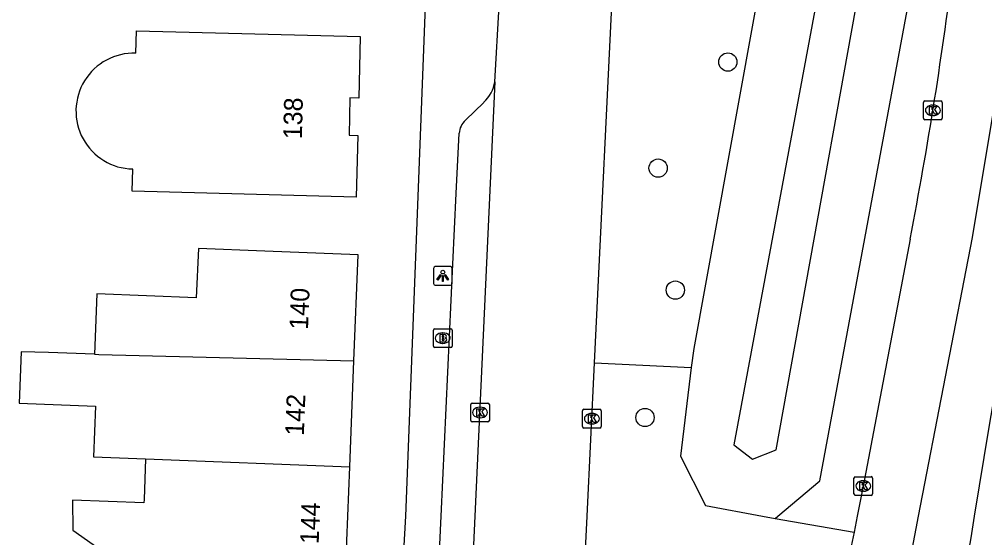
# Model space of a CAD drawing. Extents: x 160158 to 160921, y 381517 to 382041.
# Drawn here: x 160474 to 160525.6, y 381748.8 to 381776.6 of the extents above; entities that cross this region are included whole.
import ezdxf

# ---------------------------------------------------------------- set-up
doc = ezdxf.new("R2010")
doc.units = 0
for name, color, linetype in [('IMGEO_Berm_groen', 7, 'Continuous'), ('IMGEO_Boom', 7, 'Continuous'), ('IMGEO_Brandkraan', 7, 'Continuous'), ('IMGEO_Kolk', 7, 'Continuous'), ('IMGEO_Lichtpunt', 7, 'Continuous'), ('IMGEO_Pand', 7, 'Continuous'), ('IMGEO_Pand_nummerreeks', 7, 'Continuous'), ('IMGEO_Rijbaan_lokaal_open', 7, 'Continuous'), ('IMGEO_Rijbaan_regionaal_gesloten', 7, 'Continuous'), ('IMGEO_Voetpad_open', 7, 'Continuous')]:
    doc.layers.add(name, color=color, linetype=linetype)

msp = doc.modelspace()

# ---------------------------------------------------------------- linework, layer by layer
at = {"layer": 'IMGEO_Berm_groen'}
for points in [[(160520.28, 381829.952), (160520.063, 381825.981), (160517.843, 381805.586), (160514.368, 381782.689), (160510.053, 381758.978), (160509.927, 381757.953)], [(160518.254, 381786.275), (160512.205, 381753.816), (160513.2, 381753.054), (160514.475, 381753.541), (160520.343, 381786.102)], [(160514.409, 381749.874), (160514.559, 381750), (160516.8, 381751.896), (160523.052, 381785.526)], [(160504.746, 381758.207), (160509.927, 381757.953)], [(160509.927, 381757.953), (160509.344, 381753.204), (160510.68, 381750.562), (160513.728, 381750), (160514.409, 381749.874)], [(160514.409, 381749.874), (160518.635, 381749.141)]]:
    msp.add_lwpolyline(points, dxfattribs=at)
at = {"layer": 'IMGEO_Boom'}
for centre in [(160511.882, 381774.3), (160508.151, 381768.624), (160509.07, 381762.096), (160507.447, 381755.276)]:
    msp.add_circle(centre, 0.489, dxfattribs=at)
at = {"layer": 'IMGEO_Brandkraan'}
for p, q in [((160496.125, 381759.1), (160496.125, 381759.952)), ((160496.2, 381760.026), (160497.052, 381760.026)), ((160496.613, 381759.806), (160496.638, 381759.806)), ((160497.126, 381759.952), (160497.126, 381759.1)), ((160497.052, 381759.026), (160496.2, 381759.026)), ((160496.636, 381759.246), (160496.611, 381759.246))]:
    msp.add_line(p, q, dxfattribs=at)
for points in [[(160496.125, 381759.1), (160496.125, 381759.952)], [(160496.2, 381760.026), (160497.052, 381760.026)], [(160496.473, 381759.726), (160496.473, 381759.326), (160496.686, 381759.326)], [(160496.704, 381759.726), (160496.473, 381759.726)], [(160496.652, 381759.645), (160496.598, 381759.645), (160496.598, 381759.569)], [(160496.598, 381759.569), (160496.651, 381759.569)], [(160497.126, 381759.952), (160497.126, 381759.1)], [(160497.052, 381759.026), (160496.2, 381759.026)], [(160496.66, 381759.493), (160496.598, 381759.493), (160496.598, 381759.412)], [(160496.598, 381759.412), (160496.66, 381759.412)]]:
    msp.add_lwpolyline(points, dxfattribs=at)
for centre, radius, start, end in [((160496.202, 381759.95), 0.0765, 91.552, 178.448), ((160496.202, 381759.95), 0.0765, 91.552, 178.448), ((160496.653, 381759.607), 0.0379, 267.8285, 90.9355), ((160496.708, 381759.581), 0.145, 59.4692, 91.5367), ((160496.733, 381759.628), 0.0922, 285.5137, 58.1501), ((160496.738, 381759.436), 0.105, 301.3115, 78.989), ((160497.05, 381759.95), 0.0765, 1.552, 88.448), ((160497.05, 381759.95), 0.0765, 1.552, 88.448), ((160496.202, 381759.102), 0.0765, 181.552, 268.448), ((160496.202, 381759.102), 0.0765, 181.552, 268.448), ((160496.661, 381759.452), 0.0404, 269.8759, 90.5077), ((160496.692, 381759.577), 0.251, 268.6676, 293.5347), ((160497.05, 381759.102), 0.0765, 271.552, 358.448), ((160497.05, 381759.102), 0.0765, 271.552, 358.448)]:
    msp.add_arc(centre, radius, start, end, dxfattribs=at)
for centre, major_axis, ratio, start_param, end_param in [((160496.612, 381759.526), (-0.387, 0.002), 0.722429, 4.712389, 7.853982), ((160496.637, 381759.526), (-0.39, 0.002), 0.717154, 1.570796, 4.712389)]:
    msp.add_ellipse(centre, major_axis=major_axis, ratio=ratio, start_param=start_param, end_param=end_param, dxfattribs=at)
at = {"layer": 'IMGEO_Kolk'}
for p, q in [((160522.353, 381771.29), (160522.353, 381772.142)), ((160522.428, 381772.216), (160523.28, 381772.216)), ((160522.841, 381771.996), (160522.866, 381771.996)), ((160523.354, 381772.142), (160523.354, 381771.29)), ((160522.864, 381771.436), (160522.839, 381771.436)), ((160523.28, 381771.216), (160522.428, 381771.216)), ((160498.12, 381755.121), (160498.12, 381755.973)), ((160498.195, 381756.047), (160499.047, 381756.047)), ((160499.121, 381755.973), (160499.121, 381755.121)), ((160498.608, 381755.827), (160498.633, 381755.827)), ((160504.104, 381754.789), (160504.104, 381755.641)), ((160504.179, 381755.715), (160505.031, 381755.715)), ((160504.592, 381755.495), (160504.617, 381755.495)), ((160505.105, 381755.641), (160505.105, 381754.789)), ((160499.047, 381755.047), (160498.195, 381755.047)), ((160498.631, 381755.267), (160498.606, 381755.267)), ((160504.615, 381754.935), (160504.59, 381754.935)), ((160505.031, 381754.715), (160504.179, 381754.715)), ((160518.628, 381751.185), (160518.628, 381752.037)), ((160518.703, 381752.111), (160519.555, 381752.111)), ((160519.116, 381751.891), (160519.141, 381751.891)), ((160519.629, 381752.037), (160519.629, 381751.185)), ((160519.139, 381751.331), (160519.114, 381751.331)), ((160519.555, 381751.111), (160518.703, 381751.111))]:
    msp.add_line(p, q, dxfattribs=at)
for points in [[(160522.353, 381771.29), (160522.353, 381772.142)], [(160522.428, 381772.216), (160523.28, 381772.216)], [(160523.354, 381772.142), (160523.354, 381771.29)], [(160522.674, 381771.916), (160522.797, 381771.916), (160522.797, 381771.765), (160522.927, 381771.916), (160523.091, 381771.916), (160522.945, 381771.765), (160523.098, 381771.516), (160522.946, 381771.516), (160522.861, 381771.68), (160522.797, 381771.613), (160522.797, 381771.516), (160522.674, 381771.516), (160522.674, 381771.916)], [(160523.28, 381771.216), (160522.428, 381771.216)], [(160498.12, 381755.121), (160498.12, 381755.973)], [(160498.195, 381756.047), (160499.047, 381756.047)], [(160499.121, 381755.973), (160499.121, 381755.121)], [(160498.441, 381755.747), (160498.564, 381755.747), (160498.564, 381755.596), (160498.694, 381755.747), (160498.858, 381755.747), (160498.712, 381755.596), (160498.865, 381755.347), (160498.713, 381755.347), (160498.628, 381755.511), (160498.564, 381755.444), (160498.564, 381755.347), (160498.441, 381755.347), (160498.441, 381755.747)], [(160504.104, 381754.789), (160504.104, 381755.641)], [(160504.179, 381755.715), (160505.031, 381755.715)], [(160504.425, 381755.415), (160504.548, 381755.415), (160504.548, 381755.264), (160504.678, 381755.415), (160504.842, 381755.415), (160504.696, 381755.264), (160504.849, 381755.015), (160504.697, 381755.015), (160504.612, 381755.179), (160504.548, 381755.112), (160504.548, 381755.015), (160504.425, 381755.015), (160504.425, 381755.415)], [(160505.105, 381755.641), (160505.105, 381754.789)], [(160499.047, 381755.047), (160498.195, 381755.047)], [(160505.031, 381754.715), (160504.179, 381754.715)], [(160518.628, 381751.185), (160518.628, 381752.037)], [(160518.703, 381752.111), (160519.555, 381752.111)], [(160518.949, 381751.811), (160519.072, 381751.811), (160519.072, 381751.66), (160519.202, 381751.811), (160519.366, 381751.811), (160519.22, 381751.66), (160519.373, 381751.411), (160519.221, 381751.411), (160519.136, 381751.575), (160519.072, 381751.508), (160519.072, 381751.411), (160518.949, 381751.411), (160518.949, 381751.811)], [(160519.629, 381752.037), (160519.629, 381751.185)], [(160519.555, 381751.111), (160518.703, 381751.111)]]:
    msp.add_lwpolyline(points, dxfattribs=at)
for centre, start, end in [((160522.43, 381772.14), 91.552, 178.448), ((160522.43, 381772.14), 91.552, 178.448), ((160523.278, 381772.14), 1.552, 88.448), ((160523.278, 381772.14), 1.552, 88.448), ((160522.43, 381771.292), 181.552, 268.448), ((160522.43, 381771.292), 181.552, 268.448), ((160523.278, 381771.292), 271.552, 358.448), ((160523.278, 381771.292), 271.552, 358.448), ((160498.197, 381755.971), 91.552, 178.448), ((160498.197, 381755.971), 91.552, 178.448), ((160499.045, 381755.971), 1.552, 88.448), ((160499.045, 381755.971), 1.552, 88.448), ((160504.181, 381755.639), 91.552, 178.448), ((160504.181, 381755.639), 91.552, 178.448), ((160505.029, 381755.639), 1.552, 88.448), ((160505.029, 381755.639), 1.552, 88.448), ((160498.197, 381755.123), 181.552, 268.448), ((160498.197, 381755.123), 181.552, 268.448), ((160499.045, 381755.123), 271.552, 358.448), ((160499.045, 381755.123), 271.552, 358.448), ((160504.181, 381754.791), 181.552, 268.448), ((160504.181, 381754.791), 181.552, 268.448), ((160505.029, 381754.791), 271.552, 358.448), ((160505.029, 381754.791), 271.552, 358.448), ((160518.705, 381752.035), 91.552, 178.448), ((160518.705, 381752.035), 91.552, 178.448), ((160519.553, 381752.035), 1.552, 88.448), ((160519.553, 381752.035), 1.552, 88.448), ((160518.705, 381751.187), 181.552, 268.448), ((160518.705, 381751.187), 181.552, 268.448), ((160519.553, 381751.187), 271.552, 358.448), ((160519.553, 381751.187), 271.552, 358.448)]:
    msp.add_arc(centre, 0.0765, start, end, dxfattribs=at)
for centre, major_axis, ratio, start_param, end_param in [((160522.84, 381771.716), (-0.387, 0.002), 0.722429, 4.712389, 7.853982), ((160522.865, 381771.716), (-0.39, 0.002), 0.717154, 1.570796, 4.712389), ((160498.607, 381755.547), (-0.387, 0.002), 0.722429, 4.712389, 7.853982), ((160498.632, 381755.547), (-0.39, 0.002), 0.717154, 1.570796, 4.712389), ((160504.591, 381755.215), (-0.387, 0.002), 0.722429, 4.712389, 7.853982), ((160504.616, 381755.215), (-0.39, 0.002), 0.717154, 1.570796, 4.712389), ((160519.115, 381751.611), (-0.387, 0.002), 0.722429, 4.712389, 7.853982), ((160519.14, 381751.611), (-0.39, 0.002), 0.717154, 1.570796, 4.712389)]:
    msp.add_ellipse(centre, major_axis=major_axis, ratio=ratio, start_param=start_param, end_param=end_param, dxfattribs=at)
at = {"layer": 'IMGEO_Lichtpunt'}
for p, q in [((160496.131, 381763.26), (160496.131, 381762.453)), ((160496.131, 381763.26), (160496.131, 381762.453)), ((160497.033, 381763.355), (160496.225, 381763.355)), ((160497.033, 381763.355), (160496.225, 381763.355)), ((160497.127, 381762.453), (160497.127, 381763.26)), ((160497.127, 381762.453), (160497.127, 381763.26)), ((160496.225, 381762.359), (160497.033, 381762.359)), ((160496.225, 381762.359), (160497.033, 381762.359))]:
    msp.add_line(p, q, dxfattribs=at)
for points in [[(160496.505, 381762.924), (160496.544, 381762.896), (160496.356, 381762.634), (160496.318, 381762.661), (160496.505, 381762.924)], [(160496.607, 381762.876), (160496.654, 381762.876), (160496.654, 381762.554), (160496.607, 381762.554), (160496.607, 381762.876)], [(160496.717, 381762.896), (160496.755, 381762.923), (160496.942, 381762.661), (160496.903, 381762.633), (160496.717, 381762.896)]]:
    msp.add_lwpolyline(points, dxfattribs=at)
msp.add_circle((160496.63, 381763.058), 0.0994, dxfattribs=at)
for centre, start, end in [((160496.225, 381763.26), 90, 180), ((160496.225, 381763.26), 90, 180), ((160497.033, 381763.26), 0, 90), ((160497.033, 381763.26), 0, 90), ((160496.225, 381762.453), 180, 270), ((160496.225, 381762.453), 180, 270), ((160497.033, 381762.453), 270, 0), ((160497.033, 381762.453), 270, 360)]:
    msp.add_arc(centre, 0.0946, start, end, dxfattribs=at)
at = {"layer": 'IMGEO_Pand'}
for points in [[(160480.233, 381775.976), (160492.21, 381775.669), (160492.131, 381772.374), (160491.661, 381772.385), (160491.615, 381770.389), (160492.088, 381770.361), (160492.001, 381767.068), (160480.005, 381767.386), (160480.037, 381768.576)], [(160480.201, 381774.776), (160480.233, 381775.976)], [(160491.871, 381758.315), (160492.094, 381763.983), (160487.098, 381764.173), (160483.56, 381764.319), (160483.435, 381761.689), (160478.111, 381761.891), (160477.989, 381758.66)], [(160477.989, 381758.66), (160475.535, 381758.756), (160474.072, 381758.797), (160473.967, 381756.047), (160478.047, 381755.892), (160477.939, 381753.171), (160480.723, 381753.061)], [(160477.989, 381758.66), (160478.214, 381758.651), (160491.871, 381758.315)], [(160491.648, 381752.629), (160491.871, 381758.315)], [(160480.723, 381753.061), (160480.64, 381750.883), (160480.633, 381750.705), (160476.817, 381750.85), (160476.832, 381749.252), (160478.227, 381748.27)], [(160480.723, 381753.061), (160491.648, 381752.629)], [(160491.441, 381747.357), (160491.545, 381750), (160491.648, 381752.629)]]:
    msp.add_lwpolyline(points, dxfattribs=at)
msp.add_arc((160480.1, 381771.677), 3.101, 88.1345, 268.8351, dxfattribs=at)
at = {"layer": 'IMGEO_Rijbaan_lokaal_open'}
for points in [[(160499.408, 381773.249), (160499.641, 381777.308), (160499.893, 381781.775), (160499.961, 381782.679), (160499.986, 381782.965), (160500.318, 381785.755), (160500.347, 381785.986)], [(160504.746, 381758.207), (160505.796, 381779.917), (160505.903, 381781.897)], [(160499.408, 381773.249), (160498.34, 381750), (160497.464, 381731.201)], [(160504.089, 381744.624), (160504.349, 381750), (160504.746, 381758.207)]]:
    msp.add_lwpolyline(points, dxfattribs=at)
at = {"layer": 'IMGEO_Rijbaan_regionaal_gesloten'}
for points in [[(160521.362, 381746.238), (160522.088, 381750), (160524.967, 381764.913), (160526.466, 381773.924)], [(160521.633, 381764.829), (160519.13, 381751.61), (160518.807, 381750), (160518.635, 381749.141)], [(160527.375, 381763.707), (160525.853, 381754.764), (160525.07, 381750), (160524.88, 381748.845)], [(160518.635, 381749.141), (160518.486, 381748.395)]]:
    msp.add_lwpolyline(points, dxfattribs=at)
for centre, radius, start, end in [((160314.708, 381805.109), 210.809, 348.98452, 353.10404), ((160595.541, 381737.008), 71.646, 170.48995, 178.49689)]:
    msp.add_arc(centre, radius, start, end, dxfattribs=at)
at = {"layer": 'IMGEO_Voetpad_open'}
for points in [[(160495.695, 381777.781), (160494.638, 381750), (160493.473, 381729.503)], [(160497.84, 381771.183), (160498.823, 381772.144)], [(160495.794, 381734.097), (160496.54, 381750), (160497.173, 381763.481), (160497.35, 381767.257), (160497.502, 381770.49)]]:
    msp.add_lwpolyline(points, dxfattribs=at)
for centre, radius, start, end in [((160497.598, 381773.5), 1.827, 312.0966, 352.1089), ((160498.546, 381770.41), 1.047, 132.3924, 175.6074)]:
    msp.add_arc(centre, radius, start, end, dxfattribs=at)

# ---------------------------------------------------------------- texts
at = {"layer": 'IMGEO_Pand_nummerreeks'}
for s, rotation, p in [('138', 88.6678, (160489.089, 381770.162)), ('140', 87.7485, (160489.414, 381759.966)), ('142', 87.7542, (160489.191, 381754.283)), ('144', 87.7542, (160489.984, 381748.486))]:
    msp.add_text(s, height=1, rotation=rotation, dxfattribs=at).set_placement(p)

doc.saveas('drawing.dxf')
